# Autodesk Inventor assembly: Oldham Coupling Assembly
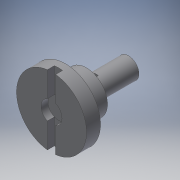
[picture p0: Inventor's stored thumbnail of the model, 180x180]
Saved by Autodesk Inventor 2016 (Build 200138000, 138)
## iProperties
Created: 2020-03
Part Number: Oldham Coupling Assembly
Document SubType Name: Assembly
Designer: Furqan
Author: Furqan
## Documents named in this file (4)
- C:\Users\Furqan\Desktop\Autodesk Inventor\C3T1. Flange_subassembly.iam
- C:\Users\Furqan\Desktop\Autodesk Inventor\C2T3. Shaft.ipt
- C:\Users\Furqan\Desktop\Autodesk Inventor\C2T2. Flange.ipt
- C:\Users\Furqan\Desktop\Autodesk Inventor\C2T4. Key.ipt
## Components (3 placed, 3 different names)
1. C2T3. Shaft:1 — Mate:1, Flush:1, Flush:3, Mate:2, Flush:4, Mate:3
2. C2T2. Flange:1 — Mate:1, Flush:1, Flush:3
3. C2T4. Key:1 — Mate:2, Flush:4, Flush:5, Mate:3
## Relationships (7: Flush 4, Mate 3)
- Mate:1: C2T3. Shaft:1 ↔ C2T2. Flange:1
- Flush:1: C2T3. Shaft:1 ↔ C2T2. Flange:1
- Flush:3: C2T3. Shaft:1 ↔ C2T2. Flange:1
- Mate:2: C2T3. Shaft:1 ↔ C2T4. Key:1
- Flush:4: C2T3. Shaft:1 ↔ C2T4. Key:1
- Flush:5: C2T4. Key:1
- Mate:3: C2T3. Shaft:1 ↔ C2T4. Key:1
